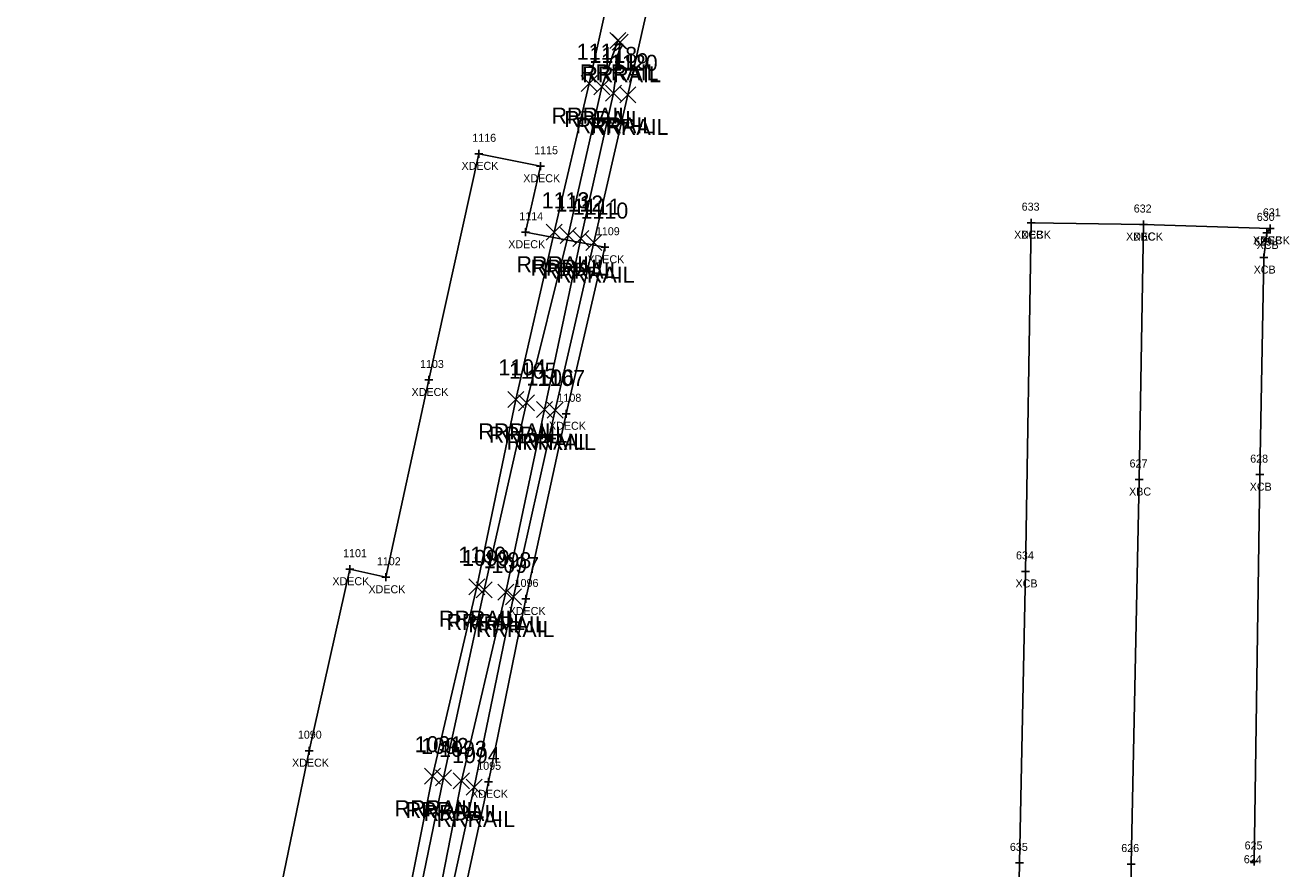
# Model space of a CAD drawing. Extents: x 1715662 to 1717487, y 887396 to 890004.
# Drawn here: x 1716478.4 to 1716636.4, y 888598.7 to 888704 of the extents above; entities that cross this region are included whole.
import ezdxf

# ---------------------------------------------------------------- set-up
doc = ezdxf.new("R2010")
doc.units = 0
for name, color, linetype in [('B_A', 7, 'Continuous'), ('B_I', 7, 'Continuous'), ('B_TIC', 7, 'Continuous'), ('BDC', 7, 'Continuous'), ('BELB', 7, 'Continuous'), ('R_A', 7, 'Continuous'), ('R_I', 7, 'Continuous'), ('R_TIC', 7, 'Continuous'), ('RR', 7, 'Continuous')]:
    doc.layers.add(name, color=color, linetype=linetype)

msp = doc.modelspace()

# ---------------------------------------------------------------- linework, layer by layer
at = {"layer": 'B_TIC'}
for p, q in [((1716535.06, 888687.95), (1716535.14, 888687.95)), ((1716535.06, 888687.95), (1716535.14, 888687.95)), ((1716542.77, 888686.4), (1716542.84, 888686.4)), ((1716540.9, 888678.16), (1716540.98, 888678.16)), ((1716604.09, 888679.35), (1716604.16, 888679.35)), ((1716604.09, 888679.35), (1716604.16, 888679.35)), ((1716618.08, 888679.12), (1716618.16, 888679.12)), ((1716618.08, 888679.12), (1716618.16, 888679.12)), ((1716633.5, 888678.07), (1716633.58, 888678.07)), ((1716633.93, 888678.64), (1716634.01, 888678.64)), ((1716633.93, 888678.64), (1716634.01, 888678.64)), ((1716550.8, 888676.28), (1716550.87, 888676.28)), ((1716633.12, 888674.99), (1716633.2, 888674.99)), ((1716528.82, 888659.7), (1716528.9, 888659.7)), ((1716545.99, 888655.48), (1716546.07, 888655.48)), ((1716617.57, 888647.27), (1716617.64, 888647.27)), ((1716632.64, 888647.88), (1716632.72, 888647.88)), ((1716518.93, 888636.07), (1716519, 888636.07)), ((1716603.38, 888635.79), (1716603.45, 888635.79)), ((1716523.44, 888635.06), (1716523.52, 888635.06)), ((1716540.95, 888632.35), (1716541.03, 888632.35)), ((1716513.89, 888613.4), (1716513.97, 888613.4)), ((1716536.26, 888609.51), (1716536.34, 888609.51)), ((1716602.62, 888599.38), (1716602.7, 888599.38)), ((1716616.56, 888599.24), (1716616.63, 888599.24)), ((1716631.94, 888599.56), (1716632.02, 888599.56))]:
    msp.add_line(p, q, dxfattribs=at)
for points in [[(1716534.56, 888687.95), (1716535.56, 888687.95)], [(1716534.56, 888687.95), (1716535.56, 888687.95)], [(1716535.06, 888687.45), (1716535.06, 888688.45)], [(1716535.06, 888687.45), (1716535.06, 888688.45)], [(1716542.26, 888686.4), (1716543.26, 888686.4)], [(1716542.76, 888685.9), (1716542.76, 888686.9)], [(1716604.08, 888678.85), (1716604.08, 888679.85)], [(1716604.08, 888678.85), (1716604.08, 888679.85)], [(1716540.4, 888678.16), (1716541.4, 888678.16)], [(1716540.9, 888677.66), (1716540.9, 888678.66)], [(1716603.58, 888679.35), (1716604.58, 888679.35)], [(1716603.58, 888679.35), (1716604.58, 888679.35)], [(1716617.58, 888679.12), (1716618.58, 888679.12)], [(1716617.58, 888679.12), (1716618.58, 888679.12)], [(1716618.08, 888678.62), (1716618.08, 888679.62)], [(1716618.08, 888678.62), (1716618.08, 888679.62)], [(1716633, 888678.07), (1716634, 888678.07)], [(1716633.43, 888678.64), (1716634.43, 888678.64)], [(1716633.43, 888678.64), (1716634.43, 888678.64)], [(1716633.5, 888677.57), (1716633.5, 888678.57)], [(1716633.93, 888678.14), (1716633.93, 888679.14)], [(1716633.93, 888678.14), (1716633.93, 888679.14)], [(1716550.79, 888675.78), (1716550.79, 888676.78)], [(1716550.29, 888676.28), (1716551.29, 888676.28)], [(1716632.62, 888674.99), (1716633.62, 888674.99)], [(1716633.12, 888674.49), (1716633.12, 888675.49)], [(1716528.32, 888659.7), (1716529.32, 888659.7)], [(1716528.82, 888659.2), (1716528.82, 888660.2)], [(1716545.99, 888654.98), (1716545.99, 888655.98)], [(1716545.49, 888655.48), (1716546.49, 888655.48)], [(1716632.64, 888647.38), (1716632.64, 888648.38)], [(1716617.06, 888647.27), (1716618.06, 888647.27)], [(1716617.56, 888646.77), (1716617.56, 888647.77)], [(1716632.14, 888647.88), (1716633.14, 888647.88)], [(1716518.43, 888636.07), (1716519.43, 888636.07)], [(1716518.93, 888635.57), (1716518.93, 888636.57)], [(1716523.44, 888634.56), (1716523.44, 888635.56)], [(1716602.87, 888635.79), (1716603.87, 888635.79)], [(1716603.37, 888635.29), (1716603.37, 888636.29)], [(1716522.94, 888635.06), (1716523.94, 888635.06)], [(1716540.45, 888632.35), (1716541.45, 888632.35)], [(1716540.95, 888631.85), (1716540.95, 888632.85)], [(1716513.39, 888613.4), (1716514.39, 888613.4)], [(1716513.89, 888612.9), (1716513.89, 888613.9)], [(1716535.76, 888609.51), (1716536.76, 888609.51)], [(1716536.26, 888609.01), (1716536.26, 888610.01)], [(1716602.12, 888599.38), (1716603.12, 888599.38)], [(1716602.62, 888598.88), (1716602.62, 888599.88)], [(1716616.05, 888599.24), (1716617.05, 888599.24)], [(1716616.55, 888598.74), (1716616.55, 888599.74)], [(1716631.44, 888599.56), (1716632.44, 888599.56)], [(1716631.94, 888599.06), (1716631.94, 888600.06)]]:
    msp.add_lwpolyline(points, dxfattribs=at)
at = {"layer": 'BDC'}
for points in [[(1716604.08, 888679.35), (1716603.37, 888635.79), (1716602.62, 888599.38), (1716601.7, 888551.65), (1716601.06, 888519.67), (1716600.26, 888472.39), (1716599.73, 888439.67), (1716598.79, 888390.75), (1716598.29, 888359.77)], [(1716631.94, 888599.56), (1716632.64, 888647.88), (1716633.12, 888674.99), (1716633.5, 888678.07), (1716633.93, 888678.64)]]:
    msp.add_lwpolyline(points, dxfattribs=at)
at = {"layer": 'BELB'}
for points in [[(1716478.41, 888445.68), (1716503.08, 888441.52), (1716508.07, 888469.67), (1716514.21, 888501.26), (1716519.96, 888529.96), (1716525.91, 888559.63), (1716530.47, 888582.92), (1716536.26, 888609.51), (1716540.95, 888632.35), (1716545.99, 888655.48), (1716550.79, 888676.28), (1716540.9, 888678.16), (1716542.76, 888686.4), (1716535.06, 888687.95)], [(1716478.41, 888445.68), (1716484.44, 888474.77), (1716490.12, 888504.65), (1716494.78, 888518.9), (1716497.76, 888535.03), (1716504.02, 888565.38), (1716508.66, 888588.18), (1716513.89, 888613.4), (1716518.93, 888636.07), (1716523.44, 888635.06), (1716528.82, 888659.7), (1716535.06, 888687.95)], [(1716633.93, 888678.64), (1716618.08, 888679.12), (1716604.08, 888679.35)], [(1716612.85, 888359.68), (1716613.89, 888403.99), (1716614.37, 888439.47), (1716614.94, 888487.77), (1716615.4, 888519.38), (1716616.36, 888571.29), (1716616.55, 888599.24), (1716617.56, 888647.27), (1716618.08, 888679.12)]]:
    msp.add_lwpolyline(points, dxfattribs=at)
at = {"layer": 'R_TIC'}
for points in [[(1716551.41, 888701.12), (1716553.41, 888703.12)], [(1716553.41, 888701.12), (1716551.41, 888703.12)], [(1716551.71, 888700.89), (1716553.71, 888702.89)], [(1716553.71, 888700.89), (1716551.71, 888702.89)], [(1716547.86, 888695.72), (1716549.86, 888697.72)], [(1716549.86, 888695.72), (1716547.86, 888697.72)], [(1716549.45, 888695.31), (1716551.45, 888697.31)], [(1716551.45, 888695.31), (1716549.45, 888697.31)], [(1716550.88, 888694.51), (1716552.88, 888696.51)], [(1716552.88, 888694.51), (1716550.88, 888696.51)], [(1716552.66, 888694.32), (1716554.66, 888696.32)], [(1716554.66, 888694.32), (1716552.66, 888696.32)], [(1716543.48, 888677.15), (1716545.48, 888679.15)], [(1716545.48, 888677.15), (1716543.48, 888679.15)], [(1716545.22, 888676.74), (1716547.22, 888678.74)], [(1716547.22, 888676.74), (1716545.22, 888678.74)], [(1716546.79, 888676.36), (1716548.79, 888678.36)], [(1716548.79, 888676.36), (1716546.79, 888678.36)], [(1716548.42, 888675.86), (1716550.42, 888677.86)], [(1716550.42, 888675.86), (1716548.42, 888677.86)], [(1716538.7, 888656.28), (1716540.7, 888658.28)], [(1716540.7, 888656.28), (1716538.7, 888658.28)], [(1716540.02, 888655.86), (1716542.02, 888657.86)], [(1716542.02, 888655.86), (1716540.02, 888657.86)], [(1716542.26, 888655.01), (1716544.26, 888657.01)], [(1716544.26, 888655.01), (1716542.26, 888657.01)], [(1716543.59, 888654.95), (1716545.59, 888656.95)], [(1716545.59, 888654.95), (1716543.59, 888656.95)], [(1716533.8, 888632.88), (1716535.8, 888634.88)], [(1716535.8, 888632.88), (1716533.8, 888634.88)], [(1716534.75, 888632.48), (1716536.75, 888634.48)], [(1716536.75, 888632.48), (1716534.75, 888634.48)], [(1716537.44, 888632.19), (1716539.44, 888634.19)], [(1716539.44, 888632.19), (1716537.44, 888634.19)], [(1716538.41, 888631.6), (1716540.41, 888633.6)], [(1716540.41, 888631.6), (1716538.41, 888633.6)], [(1716528.26, 888609.21), (1716530.26, 888611.21)], [(1716530.26, 888609.21), (1716528.26, 888611.21)], [(1716529.64, 888608.99), (1716531.64, 888610.99)], [(1716531.64, 888608.99), (1716529.64, 888610.99)], [(1716531.88, 888608.62), (1716533.88, 888610.62)], [(1716533.88, 888608.62), (1716531.88, 888610.62)], [(1716533.49, 888607.85), (1716535.49, 888609.85)], [(1716535.49, 888607.85), (1716533.49, 888609.85)]]:
    msp.add_lwpolyline(points, dxfattribs=at)
at = {"layer": 'RR'}
for points in [[(1716487.31, 888387.93), (1716492.21, 888417.1), (1716496.28, 888440.7), (1716501.72, 888471.07), (1716507.74, 888502.79), (1716513.46, 888531.59), (1716519.33, 888560.82), (1716524.17, 888584.56), (1716529.26, 888610.21), (1716534.8, 888633.88), (1716539.7, 888657.28), (1716544.48, 888678.15), (1716548.86, 888696.72), (1716554.01, 888719.92)], [(1716492.09, 888386.99), (1716497, 888416.35), (1716500.91, 888439.31), (1716506.48, 888469.5), (1716512.55, 888501.38), (1716518.26, 888530.61), (1716524.3, 888559.71), (1716528.86, 888583.15), (1716534.49, 888608.85), (1716539.41, 888632.6), (1716544.59, 888655.95), (1716549.42, 888676.86), (1716553.66, 888695.32), (1716558.99, 888718.88)], [(1716494.39, 888416.83), (1716494.94, 888422.88), (1716498.1, 888442.46), (1716502.94, 888470.67), (1716508.93, 888502.33), (1716515.06, 888531.51), (1716520.35, 888560.26), (1716525.36, 888584.29), (1716530.64, 888609.99), (1716535.75, 888633.48), (1716541.02, 888656.86), (1716546.22, 888677.74), (1716550.45, 888696.31), (1716552.41, 888702.12)], [(1716494.74, 888416.93), (1716496.25, 888422.64), (1716499.96, 888442.36), (1716505.26, 888469.46), (1716511.38, 888501.53), (1716517.25, 888530.72), (1716522.82, 888559.59), (1716527.83, 888583.61), (1716532.88, 888609.62), (1716538.44, 888633.19), (1716543.26, 888656.01), (1716547.79, 888677.36), (1716551.88, 888695.51), (1716552.71, 888701.89)]]:
    msp.add_lwpolyline(points, dxfattribs=at)

# ---------------------------------------------------------------- texts
at = {"layer": 'B_A'}
for s, p in [('XDECK', (1716532.9, 888685.95)), ('XDECK', (1716532.9, 888685.95)), ('XDECK', (1716540.61, 888684.4)), ('XDECK', (1716601.93, 888677.35)), ('XCB', (1716602.82, 888677.35)), ('XDECK', (1716615.92, 888677.12)), ('XBC', (1716616.82, 888677.12)), ('XDECK', (1716538.74, 888676.16)), ('XDECK', (1716631.77, 888676.64)), ('XCB', (1716632.24, 888676.07)), ('XCB', (1716632.67, 888676.64)), ('XDECK', (1716548.63, 888674.28)), ('XCB', (1716631.86, 888672.99)), ('XDECK', (1716526.66, 888657.7)), ('XDECK', (1716543.83, 888653.48)), ('XCB', (1716631.37, 888645.88)), ('XBC', (1716616.3, 888645.27)), ('XDECK', (1716516.77, 888634.07)), ('XDECK', (1716521.28, 888633.06)), ('XCB', (1716602.11, 888633.79)), ('XDECK', (1716538.79, 888630.35)), ('XDECK', (1716511.73, 888611.4)), ('XDECK', (1716534.1, 888607.51))]:
    msp.add_text(s, height=1, dxfattribs=at).set_placement(p)
at = {"layer": 'B_I'}
for s, p in [('1116', (1716534.25, 888689.45)), ('1116', (1716534.25, 888689.45)), ('1115', (1716541.98, 888687.9)), ('633', (1716602.88, 888680.85)), ('633', (1716602.88, 888680.85)), ('632', (1716616.88, 888680.62)), ('632', (1716616.88, 888680.62)), ('1114', (1716540.12, 888679.66)), ('630', (1716632.25, 888679.57)), ('631', (1716633.01, 888680.14)), ('631', (1716633.01, 888680.14)), ('1109', (1716549.69, 888677.78)), ('629', (1716631.91, 888676.49)), ('1103', (1716527.72, 888661.2)), ('1108', (1716544.89, 888656.98)), ('627', (1716616.36, 888648.77)), ('628', (1716631.43, 888649.38)), ('1101', (1716518.11, 888637.57)), ('1102', (1716522.33, 888636.56)), ('634', (1716602.17, 888637.29)), ('1096', (1716539.54, 888633.85)), ('1090', (1716512.46, 888614.9)), ('1095', (1716534.87, 888611.01)), ('635', (1716601.41, 888600.88)), ('626', (1716615.32, 888600.74)), ('625', (1716630.73, 888601.06)), ('624', (1716630.63, 888599.34))]:
    msp.add_text(s, height=1, dxfattribs=at).set_placement(p)
at = {"layer": 'R_A'}
for p in [(1716547.7, 888697.12), (1716548, 888696.89), (1716544.15, 888691.72), (1716545.74, 888691.31), (1716547.17, 888690.51), (1716548.95, 888690.32), (1716539.77, 888673.15), (1716541.51, 888672.74), (1716543.08, 888672.36), (1716544.72, 888671.86), (1716535, 888652.28), (1716536.31, 888651.86), (1716538.55, 888651.01), (1716539.88, 888650.95), (1716530.09, 888628.88), (1716531.04, 888628.48), (1716533.73, 888628.19), (1716534.71, 888627.6), (1716524.55, 888605.21), (1716525.93, 888604.99), (1716528.17, 888604.62), (1716529.78, 888603.85)]:
    msp.add_text('RRRAIL', height=2, dxfattribs=at).set_placement(p)
at = {"layer": 'R_I'}
for s, p in [('1117', (1716547.3, 888699.72)), ('1118', (1716548.89, 888699.31)), ('1119', (1716550.31, 888698.51)), ('1120', (1716551.45, 888698.32)), ('1113', (1716542.92, 888681.15)), ('1112', (1716544.66, 888680.74)), ('1111', (1716546.8, 888680.36)), ('1110', (1716547.78, 888679.86)), ('1104', (1716537.5, 888660.28)), ('1105', (1716538.82, 888659.86)), ('1106', (1716541, 888659.01)), ('1107', (1716542.38, 888658.95)), ('1100', (1716532.51, 888636.88)), ('1099', (1716532.97, 888636.48)), ('1098', (1716535.67, 888636.19)), ('1097', (1716536.64, 888635.6)), ('1091', (1716527.05, 888613.21)), ('1092', (1716527.86, 888612.99)), ('1093', (1716530.11, 888612.62)), ('1094', (1716531.72, 888611.85))]:
    msp.add_text(s, height=2, dxfattribs=at).set_placement(p)

doc.saveas('drawing.dxf')
